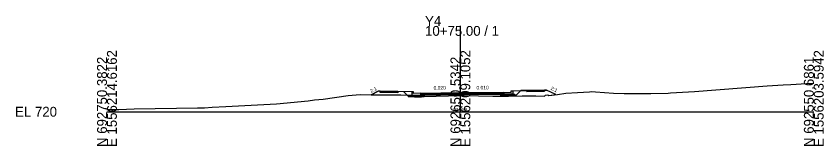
# Model space of a CAD drawing. Extents: x -26 to 203, y -10 to 1521.
# Drawn here: x -25.7 to 202.8, y 490.3 to 527.1 of the extents above; entities that cross this region are included whole.
import ezdxf

# ---------------------------------------------------------------- set-up
doc = ezdxf.new("R2010")
doc.units = 0
for name, color, linetype in [('Exist CMT Pavement', 7, 'Continuous'), ('Exist Cross Section Cell', 7, 'Continuous'), ('Exist XS Center Line Elevation Label', 7, 'Continuous'), ('Exist XS Ground Line', 7, 'Continuous'), ('Prop CMT Conc Surface', 7, 'Continuous'), ('Prop CMT Concrete Structures', 7, 'Continuous'), ('Prop CMT Pvmt Course 1', 7, 'Continuous'), ('Prop CMT Pvmt Course 1 CG', 7, 'Continuous'), ('Prop CMT Pvmt Course 2', 7, 'Continuous'), ('Prop CMT Pvmt Course 3', 7, 'Continuous'), ('Prop CMT Pvmt Surface', 7, 'Continuous'), ('Prop CMT Slope Grass', 7, 'Continuous'), ('Prop CMT Subgrade Earthwork', 7, 'Continuous'), ('Prop XS Earthwork Shape', 7, 'Continuous'), ('Prop XS SE Text', 7, 'Continuous'), ('Prop XS Side Slope Text', 7, 'Continuous')]:
    doc.layers.add(name, color=color, linetype=linetype)

msp = doc.modelspace()

# ---------------------------------------------------------------- linework, layer by layer
at = {"layer": 'Exist CMT Pavement'}
for p, q in [((89.77, 504.28), (100, 504.58)), ((100, 504.58), (101.07, 504.61)), ((101.07, 504.61), (109.15, 504.38)), ((109.15, 504.38), (111.34, 504.4))]:
    msp.add_line(p, q, dxfattribs=at)
at = {"layer": 'Exist Cross Section Cell'}
for p, q in [((100, 500), (100, 524.34)), ((0, 500), (100, 500)), ((100, 500), (200, 500))]:
    msp.add_line(p, q, dxfattribs=at)
at = {"layer": 'Exist XS Ground Line'}
msp.add_lwpolyline([(0, 500.68), (3.39, 500.66), (7.66, 500.8), (25.63, 501.13), (27.6, 501.15), (29.77, 501.25), (33.67, 501.47), (47.99, 502.23), (56.97, 503.11), (58.71, 503.39), (61.18, 503.56), (68.23, 504.65), (71.61, 504.9), (75.31, 504.81), (78.31, 504.84), (78.88, 504.83), (83.12, 504.79), (86.48, 504.67), (87.11, 504.26), (88.99, 504.27), (89.77, 504.28), (100, 504.58), (101.07, 504.61), (109.15, 504.38), (113.64, 504.42), (117.5, 504.49), (121.37, 504.5), (123.81, 504.45), (124.11, 504.68), (124.71, 504.82), (125.06, 504.65), (127.51, 504.91), (129.82, 505.24), (133.1, 505.42), (136.5, 505.68), (137.21, 505.72), (138.26, 505.68), (143.34, 505.28), (146.36, 505.17), (150.15, 505.13), (153.88, 505.2), (158.78, 505.29), (159.42, 505.34), (166.27, 505.74), (186.77, 507.31), (191.33, 507.61), (193.46, 507.73), (197.96, 508.03), (200, 508.11)], dxfattribs=at)
at = {"layer": 'Prop CMT Conc Surface'}
for points in [[(82.27, 505.72), (77.27, 505.82)], [(86.77, 505.13), (86.77, 505.63), (86.27, 505.63)], [(88.77, 505.25), (86.77, 505.13)], [(112.34, 505.59), (114.34, 505.47)], [(114.34, 505.47), (114.34, 505.97), (114.84, 505.97)], [(118.84, 506.06), (123.84, 506.16)]]:
    msp.add_lwpolyline(points, dxfattribs=at)
at = {"layer": 'Prop CMT Concrete Structures'}
for points in [[(77.27, 505.48), (77.27, 505.82)], [(77.27, 505.82), (82.27, 505.72)], [(82.27, 505.38), (77.27, 505.48)], [(82.27, 505.72), (82.27, 505.38)], [(88.77, 505.25), (86.77, 505.13), (86.77, 505.63), (86.27, 505.63)], [(86.27, 505.63), (86.27, 504.61), (88.77, 504.66)], [(88.77, 504.66), (88.77, 505.25)], [(112.34, 505.59), (114.34, 505.47), (114.34, 505.97), (114.84, 505.97)], [(114.84, 505.97), (114.84, 504.96), (112.34, 505.01)], [(112.34, 505.01), (112.34, 505.59)], [(123.84, 506.16), (118.84, 506.06)], [(118.84, 506.06), (118.84, 505.73)], [(118.84, 505.73), (123.84, 505.83)], [(123.84, 505.83), (123.84, 506.16)]]:
    msp.add_lwpolyline(points, dxfattribs=at)
at = {"layer": 'Prop CMT Pvmt Course 1'}
for p, q in [((89.77, 505.14), (100, 505.35)), ((89.77, 505.14), (89.77, 505.02)), ((100, 505.35), (111.34, 505.46)), ((111.34, 505.46), (111.34, 505.33))]:
    msp.add_line(p, q, dxfattribs=at)
for points in [[(88.77, 505.25), (88.77, 505)], [(100, 505.47), (112.34, 505.59)], [(100, 505.47), (100, 505.22)], [(100, 505.22), (100, 505.47)], [(112.34, 505.34), (100, 505.22)], [(112.34, 505.59), (112.34, 505.34)]]:
    msp.add_lwpolyline(points, dxfattribs=at)
msp.add_lwpolyline([(100, 505.22), (100, 505.35), (100, 505.35), (100, 505.22)], close=True, dxfattribs=at)
at = {"layer": 'Prop CMT Pvmt Course 1 CG'}
for points in [[(88.77, 504.66), (85.77, 504.6), (85.43, 504.26)], [(85.43, 504.26), (88.77, 504.33)], [(88.77, 504.41), (88.77, 504.66)], [(112.34, 505.01), (115.34, 504.95), (115.68, 504.61)], [(112.34, 504.76), (112.34, 505.01)], [(115.68, 504.61), (112.34, 504.68)]]:
    msp.add_lwpolyline(points, dxfattribs=at)
at = {"layer": 'Prop CMT Pvmt Course 2'}
for p, q in [((88.77, 505), (100, 505.22)), ((111.34, 505.33), (111.34, 505)), ((89.77, 505.02), (89.77, 504.68))]:
    msp.add_line(p, q, dxfattribs=at)
for points in [[(100, 505.22), (112.34, 505.34)], [(100, 505.22), (100, 504.89)], [(100, 504.89), (100, 505.22)], [(100, 504.89), (100, 505.22)], [(100, 504.89), (100, 505.22)], [(112.34, 505.34), (112.34, 505.01)], [(88.77, 505), (88.77, 504.66)], [(112.34, 505.01), (100, 504.89)]]:
    msp.add_lwpolyline(points, dxfattribs=at)
at = {"layer": 'Prop CMT Pvmt Course 3'}
for p, q in [((88.77, 504.66), (100, 504.89)), ((89.77, 504.68), (89.77, 504.35)), ((111.34, 505), (111.34, 504.67))]:
    msp.add_line(p, q, dxfattribs=at)
for points in [[(88.77, 504.66), (88.77, 504.33)], [(100, 504.89), (112.34, 505.01)], [(112.34, 505.01), (112.34, 504.68)]]:
    msp.add_lwpolyline(points, dxfattribs=at)
at = {"layer": 'Prop CMT Pvmt Surface'}
msp.add_line((88.77, 505.25), (100, 505.47), dxfattribs=at)
msp.add_lwpolyline([(100, 505.47), (112.34, 505.59)], dxfattribs=at)
at = {"layer": 'Prop CMT Slope Grass'}
for p, q in [((74.79, 504.83), (76.77, 505.82)), ((126.96, 504.85), (124.34, 506.16))]:
    msp.add_line(p, q, dxfattribs=at)
for points in [[(86.27, 505.63), (76.77, 505.82)], [(114.84, 505.97), (124.34, 506.16)]]:
    msp.add_lwpolyline(points, dxfattribs=at)
at = {"layer": 'Prop CMT Subgrade Earthwork'}
for p, q in [((88.77, 504.33), (89.77, 504.35)), ((89.77, 504.35), (89.77, 504.28)), ((111.34, 504.67), (112.34, 504.68)), ((111.34, 504.67), (111.34, 504.4))]:
    msp.add_line(p, q, dxfattribs=at)
for points in [[(88.77, 504.33), (85.43, 504.26), (84.02, 505.67)], [(112.34, 504.68), (115.68, 504.61), (117.09, 506.02)]]:
    msp.add_lwpolyline(points, dxfattribs=at)
at = {"layer": 'Prop XS Earthwork Shape'}
for points in [[(84.97, 504.72), (84.02, 505.68), (82.27, 505.72), (82.27, 505.38), (77.27, 505.48), (77.27, 505.82), (76.77, 505.82), (74.79, 504.83), (75.31, 504.81), (78.31, 504.84), (78.88, 504.83), (83.12, 504.79)], [(126.96, 504.85), (124.34, 506.16), (123.84, 506.16), (123.84, 505.83), (118.84, 505.73), (118.84, 506.06), (117.09, 506.03), (115.68, 504.61), (112.34, 504.68), (111.34, 504.67), (111.34, 504.4), (113.64, 504.42), (117.5, 504.49), (121.37, 504.5), (123.81, 504.45), (124.11, 504.68), (124.71, 504.82), (125.06, 504.65)], [(85.43, 504.26), (84.97, 504.72), (86.27, 504.67), (86.27, 504.61), (86.55, 504.62), (87.06, 504.3)], [(86.27, 504.61), (86.55, 504.62), (86.48, 504.67), (86.27, 504.67)], [(88.77, 504.33), (87.06, 504.3), (87.11, 504.26), (88.99, 504.27), (89.77, 504.28), (89.77, 504.35)]]:
    msp.add_lwpolyline(points, close=True, dxfattribs=at)

# ---------------------------------------------------------------- texts
at = {"layer": 'Exist Cross Section Cell'}
for s, p in [('Y4', (90, 524.34)), ('10+75.00 / 1', (90, 521.54)), ('EL 720', (-26, 498.6))]:
    msp.add_text(s, height=2.8, dxfattribs=at).set_placement(p)
for s, p in [('E 1556214.6162', (2.8, 490)), ('E 1556209.1052', (102.8, 490)), ('E 1556203.5942', (202.8, 490)), ('N 692750.3822', (0, 490)), ('N 692650.5342', (100, 490)), ('N 692550.6861', (200, 490))]:
    msp.add_text(s, height=2.8, rotation=90, dxfattribs=at).set_placement(p)
at = {"layer": 'Exist XS Center Line Elevation Label'}
msp.add_text('724.58', height=1, dxfattribs=at).set_placement((97.75, 500.08))
at = {"layer": 'Prop XS SE Text'}
for s, rotation, p in [('0.010', 0.5729, (104.56, 506.33)), ('0.020', 0.843, (92.43, 506.28))]:
    msp.add_text(s, height=1, rotation=rotation, dxfattribs=at).set_placement(p)
at = {"layer": 'Prop XS Side Slope Text'}
for rotation, p in [(26.5651, (74.79, 505.36)), (333.4349, (125.44, 506.32))]:
    msp.add_text('2:1', height=1, rotation=rotation, dxfattribs=at).set_placement(p)

doc.saveas('drawing.dxf')
